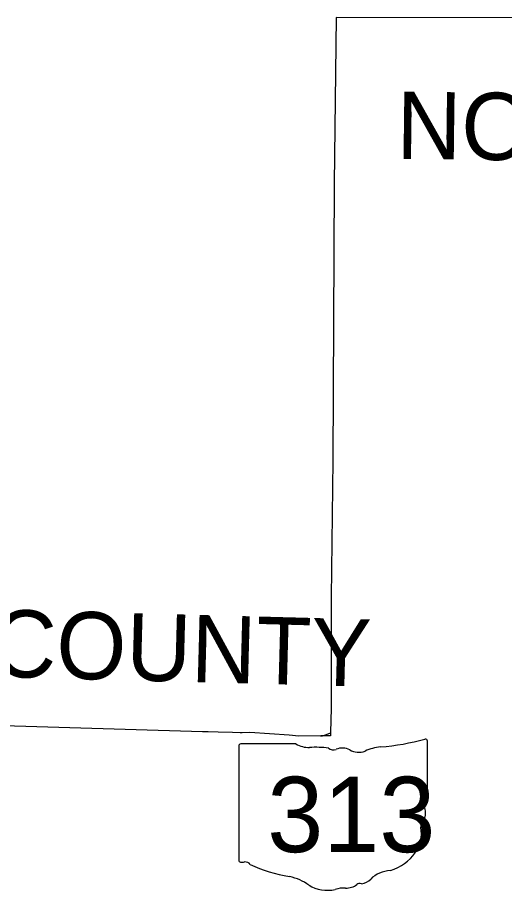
# Model space of a CAD drawing. Extents: x 2125567 to 2397567, y 653347 to 829347.
# Drawn here: x 2276068 to 2283311, y 699437 to 712433 of the extents above; entities that cross this region are included whole.
import ezdxf

# ---------------------------------------------------------------- set-up
doc = ezdxf.new("R2010")
doc.units = 0
for name, color, linetype in [('GM_X_County', 7, 'Continuous'), ('GM_X_County_Text', 7, 'Continuous'), ('GM_X_State_Route', 7, 'Continuous'), ('GM_X_State_Shield', 7, 'Continuous')]:
    doc.layers.add(name, color=color, linetype=linetype)

msp = doc.modelspace()

# ---------------------------------------------------------------- linework, layer by layer
at = {"layer": 'GM_X_County'}
msp.add_lwpolyline([(2283616, 712429), (2280806, 712433), (2280776, 709965), (2280757, 705844), (2280731, 703815), (2280732, 702480), (2280732, 702166), (2280722, 701801), (2280723, 701750), (2280577, 701750), (2280250, 701746), (2280110, 701764), (2279525, 701800), (2279408, 701795), (2279378, 701797), (2279266, 701801), (2279054, 701809), (2278904, 701811), (2278868, 701812), (2278821, 701811), (2274543, 701942)], dxfattribs=at)
at = {"layer": 'GM_X_State_Route'}
msp.add_lwpolyline([(2280578, 701747), (2280602, 701753), (2280650, 701768), (2280665, 701773), (2280723, 701798)], dxfattribs=at)
at = {"layer": 'GM_X_State_Shield'}
for p, q in [((2282163, 700785), (2282163, 701675)), ((2279361, 701604), (2279361, 699903)), ((2280209, 701633), (2279389, 701633)), ((2282162, 700786), (2282163, 700785))]:
    msp.add_line(p, q, dxfattribs=at)
for centre, major_axis, start_param, end_param in [((2281165, 703952), (2971, 0), 4.814394, 5.042369), ((2282132, 701679), (31.2, 0), 6.141152, 7.989035), ((2279393, 701607), (32.5, 0), 1.712693, 3.28349), ((2280405, 701831), (315, 0), 4.042523, 4.731795), ((2280509, 700678), (1130, 0), 1.404758, 1.657858), ((2280765, 701616), (90.8, 0), 3.836095, 5.185415), ((2280899, 701420), (189, 0), 0.950623, 2.079405), ((2281143, 701689), (227, 0), 4.081561, 5.145723), ((2281544, 701114), (598, 0), 1.699011, 2.107814), ((2282156, 700720), (48.3, 0), 1.883978, 3.671073), ((2282129, 700782), (33.4, 0), 5.05454, 6.418171), ((2281848, 700608), (290, 0), 5.934695, 6.695948), ((2282274, 700413), (211, 0), 2.387724, 3.262537), ((2281331, 700300), (743, 0), 5.101752, 6.440018), ((2279393, 699899), (32.7, 0), 3.00124, 4.508301), ((2279398, 700073), (250, 0), 4.665946, 4.897461), ((2279450, 699805), (90.1, 0), 0.519207, 1.627899), ((2280587, 701333), (2146, 0), 4.195997, 4.488961), ((2281645, 699425), (407, 0), 1.647645, 2.488434), ((2279947, 699138), (671, 0), 0.823519, 1.323587), ((2281129, 699738), (240, 0), 4.937069, 5.64225), ((2280674, 699796), (426, 0), 4.026481, 4.996735), ((2280920, 699208), (350, 0), 1.495662, 1.94098), ((2280951, 699669), (227, 0), 4.691044, 5.507374), ((2281156, 699504), (63.9, 0), 1.147584, 2.315152)]:
    msp.add_ellipse(centre, major_axis=major_axis, ratio=0.8, start_param=start_param, end_param=end_param, dxfattribs=at)

# ---------------------------------------------------------------- texts
at = {"layer": 'GM_X_County_Text'}
for s, rotation, p in [('NOBLE COUNTY', 359.2846, (2281699, 710333)), ('GUERNSEY COUNTY', 358.4647, (2267795, 702844))]:
    msp.add_text(s, height=1000, rotation=rotation, dxfattribs=at).set_placement(p)
at = {"layer": 'GM_X_State_Shield'}
msp.add_text('313', height=1120.7, dxfattribs=at).set_placement((2279782, 700023))

doc.saveas('drawing.dxf')
